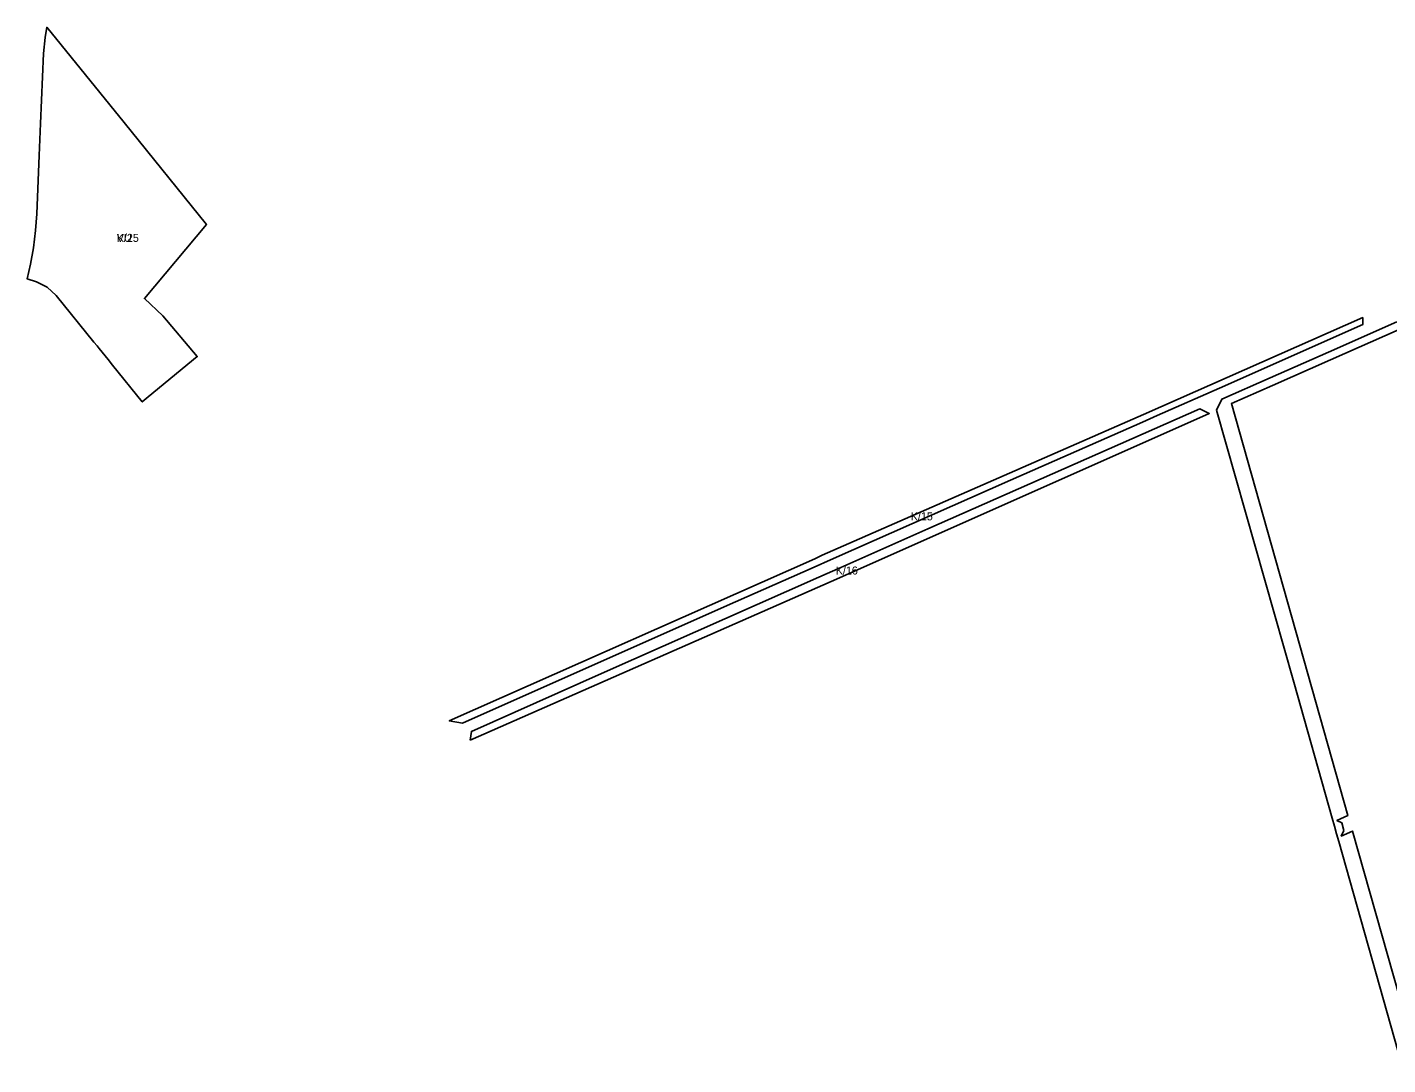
# Model space of a CAD drawing. Extents: x -521969 to -519862, y -1142171 to -1140238.
# Drawn here: x -521969 to -521119, y -1141487 to -1140839 of the extents above; entities that cross this region are included whole.
import ezdxf

# ---------------------------------------------------------------- set-up
doc = ezdxf.new("R2010")
doc.units = 0
doc.layers.add('96111023', color=7, linetype='Continuous')
doc.layers.add('96141023', color=7, linetype='Continuous')

msp = doc.modelspace()

# ---------------------------------------------------------------- linework, layer by layer
at = {"layer": '96111023'}
for points in [[(-521966.75, -1140986.81), (-521964.79, -1140976.78), (-521963.61, -1140965.78), (-521962.64, -1140955.52), (-521961.27, -1140919.13), (-521960.41, -1140899.15), (-521958.48, -1140855.25), (-521957.55, -1140845.37), (-521956.51, -1140838.94), (-521908.14, -1140898.33), (-521856.78, -1140962.03), (-521895.5, -1141008.4), (-521884.07, -1141019.15), (-521862.5, -1141044.56), (-521893.06, -1141069.8), (-521896.82, -1141072.9), (-521915.45, -1141049.99), (-521918.24, -1141046.46), (-521923.77, -1141039.61), (-521925.13, -1141037.95), (-521927.04, -1141035.61), (-521950.59, -1141006.47), (-521956.25, -1141001.25), (-521962.85, -1140997.93), (-521968.74, -1140996.16)], [(-521476.67, -1141170.91), (-521472.07, -1141168.66), (-521274.53, -1141082.16), (-521271.3, -1141080.74), (-521134.23, -1141020.21), (-521134.18, -1141024.63), (-521223.67, -1141064.26), (-521262.72, -1141081.47), (-521271.86, -1141085.49), (-521354.37, -1141121.84), (-521464.85, -1141170.68), (-521478.81, -1141176.87), (-521531.28, -1141200.09), (-521696.71, -1141273.51), (-521705, -1141272.16)], [(-521692.02, -1141284.07), (-521691.15, -1141278.7), (-521609.81, -1141242.59), (-521474.13, -1141182.35), (-521460.33, -1141176.23), (-521405.94, -1141152.24), (-521236.08, -1141077.32), (-521230.09, -1141080.11), (-521461.21, -1141182.74), (-521466.3, -1141184.96)]]:
    msp.add_lwpolyline(points, close=True, dxfattribs=at)
for points in [[(-521109.72, -1141486.85), (-521149.23, -1141347.36), (-521150.52, -1141342.71), (-521151.86, -1141337.89), (-521153.24, -1141332.9), (-521177.35, -1141247.92), (-521225.53, -1141078.04), (-521222.3, -1141071.25), (-521191.96, -1141057.88), (-521155.63, -1141041.85), (-521112.83, -1141022.98)], [(-521111.47, -1141027.75), (-521154.28, -1141046.62), (-521190.59, -1141062.63), (-521216.29, -1141073.97), (-521143.42, -1141331.19), (-521150.33, -1141334.27), (-521147.33, -1141335.67), (-521146.08, -1141340.6), (-521147.68, -1141344.03), (-521140.66, -1141340.91), (-521100.48, -1141482.76)]]:
    msp.add_lwpolyline(points, dxfattribs=at)
at = {"layer": '96141023'}
msp.add_lwpolyline([(-521966.75, -1140986.81), (-521964.79, -1140976.78), (-521963.61, -1140965.78), (-521962.64, -1140955.52), (-521961.27, -1140919.13), (-521960.41, -1140899.15), (-521958.48, -1140855.25), (-521957.55, -1140845.37), (-521956.51, -1140838.94), (-521908.14, -1140898.33), (-521856.78, -1140962.03), (-521895.5, -1141008.4), (-521884.07, -1141019.15), (-521862.5, -1141044.56), (-521893.06, -1141069.8), (-521896.82, -1141072.9), (-521915.45, -1141049.99), (-521918.24, -1141046.46), (-521923.77, -1141039.61), (-521925.13, -1141037.95), (-521927.04, -1141035.61), (-521950.59, -1141006.47), (-521956.25, -1141001.25), (-521962.85, -1140997.93), (-521968.74, -1140996.16)], close=True, dxfattribs=at)

# ---------------------------------------------------------------- texts
at = {"layer": '96111023'}
for s, rotation, p in [('K/25', 360, (-521912.76, -1140972.98)), ('K/15', 0, (-521416.63, -1141146.86)), ('K/16', 0, (-521463.5, -1141180.7))]:
    msp.add_text(s, height=5, rotation=rotation, dxfattribs=at).set_placement(p)
at = {"layer": '96141023'}
msp.add_text('VU', height=5, rotation=360, dxfattribs=at).set_placement((-521912.76, -1140972.98))

doc.saveas('drawing.dxf')
